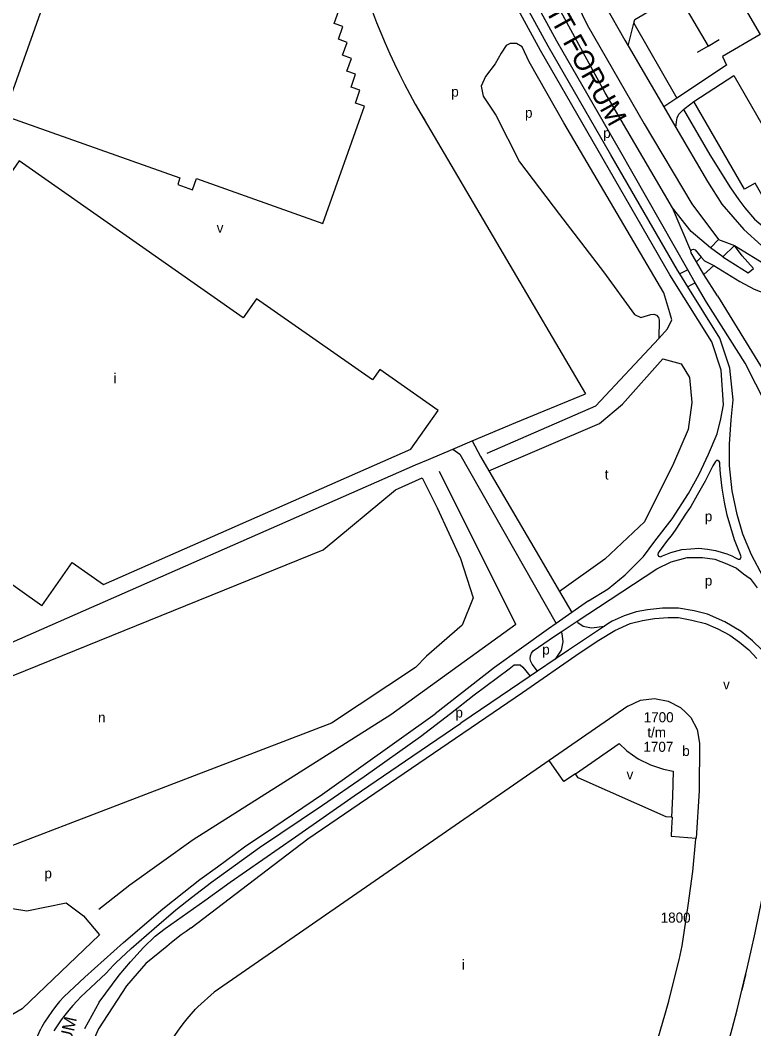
# Model space of a CAD drawing. Extents: x 154765 to 156627, y 383996 to 386132.
# Drawn here: x 155703.2 to 155994.8, y 384500 to 384900.8 of the extents above; entities that cross this region are included whole.
import ezdxf

# ---------------------------------------------------------------- set-up
doc = ezdxf.new("R2010")
doc.units = 0
for name, color, linetype in [('BLT_Basislijn', 7, 'Continuous'), ('BLT_Bebouwing', 7, 'Continuous'), ('BLT_Centroide', 7, 'Continuous'), ('BLT_Huisnummer_reeks', 7, 'Continuous'), ('BLT_Onderverdeling_panden', 7, 'Continuous'), ('BLT_Straatnaam', 7, 'Continuous'), ('BLT_Straatnaam_hoofdweg', 7, 'Continuous'), ('BLT_Vlakafsluiter', 7, 'Continuous')]:
    doc.layers.add(name, color=color, linetype=linetype)

msp = doc.modelspace()

# ---------------------------------------------------------------- linework, layer by layer
at = {"layer": 'BLT_Basislijn'}
for p, q in [((155965.14, 384910.17), (155976.62, 384890.53)), ((155843.24, 384904.14), (155844.83, 384899.94)), ((155844.83, 384899.94), (155846.5, 384895.78)), ((155944.9, 384890.58), (155947.12, 384899.61)), ((155947.12, 384899.61), (155964.19, 384869.82)), ((155846.5, 384895.78), (155848.25, 384891.64)), ((155848.25, 384891.64), (155850.07, 384887.53)), ((155976.62, 384890.53), (155980.95, 384893.19)), ((155850.07, 384887.53), (155851.96, 384883.46)), ((155976.62, 384890.53), (155972.24, 384888.03)), ((155851.96, 384883.46), (155853.92, 384879.42)), ((155853.92, 384879.42), (155855.96, 384875.41)), ((155855.96, 384875.41), (155858.06, 384871.45)), ((155858.06, 384871.45), (155860.24, 384867.52)), ((155964.19, 384869.82), (155959.04, 384866.38)), ((155862.48, 384863.63), (155863.99, 384861.1)), ((155987.12, 384811.23), (156000.44, 384803.04)), ((155968.54, 384801.65), (155965.34, 384800.02)), ((155968.59, 384794.83), (155965.34, 384800.02)), ((155971.5, 384796.52), (155968.54, 384801.65)), ((155957.02, 384774.37), (155960.53, 384778.12)), ((155900.14, 384740.9), (155927.92, 384752.37)), ((155981.67, 384742.4), (155982.74, 384747.99)), ((155985.75, 384741.97), (155986.61, 384749.93)), ((155889.46, 384721.75), (155933.46, 384740.57)), ((155980.16, 384736.38), (155981.67, 384742.4)), ((155985.11, 384732.29), (155985.75, 384741.97)), ((155976.72, 384728.42), (155980.16, 384736.38)), ((155985.11, 384723.68), (155985.11, 384732.29)), ((155973.07, 384720.46), (155976.72, 384728.42)), ((155978.54, 384723.67), (155975.49, 384717.57)), ((155979.55, 384725.5), (155978.54, 384723.67)), ((155979.96, 384725.8), (155979.55, 384725.5)), ((155980.47, 384725.8), (155979.96, 384725.8)), ((155980.97, 384725.5), (155980.47, 384725.8)), ((155981.28, 384724.99), (155980.97, 384725.5)), ((155981.28, 384724.18), (155981.28, 384724.99)), ((155981.48, 384720.52), (155981.28, 384724.18)), ((155986.18, 384713.79), (155985.11, 384723.68)), ((155900.15, 384660.61), (155869.89, 384721.5)), ((155889.46, 384721.75), (155908.25, 384689.69)), ((155968.77, 384712.71), (155973.07, 384720.46)), ((155982.19, 384714.83), (155981.48, 384720.52)), ((155975.49, 384717.57), (155972.24, 384712.09)), ((155983.11, 384709.24), (155982.19, 384714.83)), ((155962.32, 384702.6), (155968.77, 384712.71)), ((155972.24, 384712.09), (155969.7, 384707.62)), ((155988.12, 384704.32), (155986.18, 384713.79)), ((155969.7, 384707.62), (155967.88, 384704.87)), ((155984.22, 384704.16), (155983.11, 384709.24)), ((155967.88, 384704.87), (155965.95, 384701.83)), ((155987.17, 384694.31), (155984.22, 384704.16)), ((155990.48, 384696.58), (155988.12, 384704.32)), ((155955.43, 384693.78), (155962.32, 384702.6)), ((155964.02, 384698.98), (155962.29, 384696.44)), ((155965.95, 384701.83), (155964.02, 384698.98)), ((155962.29, 384696.44), (155960.06, 384693.6)), ((155993.92, 384688.4), (155990.48, 384696.58)), ((155950.92, 384687.76), (155955.43, 384693.78)), ((155960.06, 384693.6), (155957.2, 384689.71)), ((155966.15, 384690.45), (155969.7, 384690.75)), ((155969.7, 384690.75), (155972.95, 384690.96)), ((155972.95, 384690.96), (155976.4, 384690.55)), ((155989.5, 384688.31), (155987.17, 384694.31)), ((155908.25, 384689.69), (155917.54, 384673.85)), ((155943.61, 384680.44), (155950.92, 384687.76)), ((155956.81, 384689.13), (155956.61, 384688.52)), ((155956.61, 384688.52), (155956.91, 384687.86)), ((155957.2, 384689.71), (155956.81, 384689.13)), ((155956.91, 384687.86), (155957.71, 384687.58)), ((155957.71, 384687.58), (155958.53, 384687.91)), ((155958.53, 384687.91), (155961.78, 384689.23)), ((155961.78, 384689.23), (155966.15, 384690.45)), ((155961.89, 384685.61), (155968.34, 384687.33)), ((155968.34, 384687.33), (155974.36, 384687.33)), ((155974.36, 384687.33), (155979.3, 384686.68)), ((155976.4, 384690.55), (155979.55, 384690.04)), ((155979.3, 384686.68), (155984.03, 384684.75)), ((155979.55, 384690.04), (155981.79, 384689.43)), ((155981.79, 384689.43), (155984.02, 384688.72)), ((155984.02, 384688.72), (155986.05, 384687.91)), ((155986.05, 384687.91), (155987.57, 384687.1)), ((155987.57, 384687.1), (155988.59, 384686.59)), ((155989.3, 384686.59), (155989.81, 384687.5)), ((155989.81, 384687.5), (155989.5, 384688.31)), ((155998.44, 384679.58), (155993.92, 384688.4)), ((155933.12, 384667.6), (155956.3, 384682.81)), ((155956.3, 384682.81), (155961.89, 384685.61)), ((155984.03, 384684.75), (155987.9, 384683.03)), ((155987.9, 384683.03), (155990.7, 384680.87)), ((155988.59, 384686.59), (155989.3, 384686.59)), ((155936.94, 384674.85), (155943.61, 384680.44)), ((155990.7, 384680.87), (155993.28, 384678.94)), ((155993.28, 384678.94), (155996.07, 384675.28)), ((155929.13, 384670.04), (155936.94, 384674.85)), ((155917.54, 384673.85), (155922.49, 384665.4)), ((155958.55, 384667.17), (155952.52, 384666.52)), ((155964.8, 384667.17), (155958.55, 384667.17)), ((155971.05, 384666.09), (155964.8, 384667.17)), ((155943.26, 384664.15), (155938.52, 384662)), ((155948, 384665.66), (155943.26, 384664.15)), ((155952.52, 384666.52), (155948, 384665.66)), ((155950.59, 384662.21), (155955.32, 384663.07)), ((155955.32, 384663.07), (155960.71, 384663.5)), ((155960.71, 384663.5), (155964.8, 384663.5)), ((155964.8, 384663.5), (155970.18, 384662.43)), ((155976.43, 384664.8), (155971.05, 384666.09)), ((155983.32, 384661.78), (155976.43, 384664.8)), ((155939.6, 384658.33), (155945.63, 384661.13)), ((155945.63, 384661.13), (155950.59, 384662.21)), ((155970.18, 384662.43), (155975.57, 384661.13)), ((155975.57, 384661.13), (155980.52, 384658.98)), ((155980.52, 384658.98), (155985.26, 384656.39)), ((155989.78, 384657.9), (155983.32, 384661.78)), ((155933.14, 384654.45), (155939.6, 384658.33)), ((155985.26, 384656.39), (155989.14, 384653.59)), ((155994.3, 384654.24), (155989.78, 384657.9)), ((155925.82, 384649.5), (155933.14, 384654.45)), ((155989.14, 384653.59), (155992.8, 384650.58)), ((155992.8, 384650.58), (155996.03, 384647.13)), ((155997.96, 384650.58), (155994.3, 384654.24)), ((155902.9, 384633.69), (155925.82, 384649.5)), ((155905.9, 384647.09), (155905.99, 384648.16)), ((155906.23, 384645.94), (155905.9, 384647.09)), ((155905.99, 384648.16), (155906.41, 384649.26)), ((155906.41, 384649.26), (155907.1, 384650.14)), ((155915.89, 384646.94), (155908.79, 384642.11)), ((155921.12, 384650.51), (155915.89, 384646.94)), ((155891.79, 384643.6), (155868.18, 384625.12)), ((155883.61, 384632.74), (155897.61, 384643.08)), ((155897.61, 384643.08), (155899.55, 384644.59)), ((155899.55, 384644.59), (155901.92, 384644.59)), ((155901.92, 384644.59), (155902.99, 384643.72)), ((155902.99, 384643.72), (155905.9, 384640.14)), ((155906.74, 384644.9), (155906.23, 384645.94)), ((155908.79, 384642.11), (155906.74, 384644.9)), ((155905.9, 384640.14), (155878.3, 384621.52)), ((155908.79, 384642.11), (155905.9, 384640.14)), ((155817.6, 384575.48), (155902.9, 384633.69)), ((155874.18, 384625.29), (155883.61, 384632.74)), ((155823.43, 384593.22), (155868.18, 384625.12)), ((155862.35, 384616.2), (155874.18, 384625.29)), ((155859.27, 384608.48), (155878.3, 384621.52)), ((155839.89, 384600.25), (155862.35, 384616.2)), ((155835.95, 384592.53), (155859.27, 384608.48)), ((155823.43, 384588.93), (155839.89, 384600.25)), ((155804.06, 384580.18), (155823.43, 384593.22)), ((155812.63, 384576.23), (155835.95, 384592.53)), ((155798.4, 384572.11), (155823.43, 384588.93)), ((155792.4, 384572.29), (155804.06, 384580.18)), ((155786.74, 384558.22), (155812.63, 384576.23)), ((155801.44, 384563.18), (155817.6, 384575.48)), ((155779.2, 384558.22), (155798.4, 384572.11)), ((155781.6, 384564.4), (155792.4, 384572.29)), ((155771.22, 384540.07), (155801.44, 384563.18)), ((155774.62, 384559.31), (155781.6, 384564.4)), ((155768.25, 384554.24), (155774.62, 384559.31)), ((155771.36, 384552.12), (155779.2, 384558.22)), ((155776.58, 384550.97), (155786.74, 384558.22)), ((155759.92, 384547.7), (155768.25, 384554.24)), ((155760.9, 384539.85), (155776.58, 384550.97)), ((155765.15, 384547.21), (155771.36, 384552.12)), ((155744.23, 384534.29), (155759.92, 384547.7)), ((155756.49, 384539.85), (155765.15, 384547.21)), ((155747.33, 384531.84), (155756.49, 384539.85)), ((155756.81, 384536.75), (155760.9, 384539.85)), ((155752.24, 384532.33), (155756.81, 384536.75)), ((155728.87, 384520.56), (155744.23, 384534.29)), ((155741.19, 384526.22), (155747.33, 384531.84)), ((155747.01, 384526.61), (155752.24, 384532.33)), ((155720.54, 384512.72), (155728.87, 384520.56)), ((155737.4, 384522.15), (155729.19, 384514.43)), ((155988.13, 384507.59), (155991.54, 384521.43)), ((155991.54, 384521.43), (155990.07, 384515.31)), ((155986.14, 384500), (155988.13, 384507.59)), ((155982.27, 384486.09), (155986.13, 384499.98)), ((155986.13, 384499.98), (155986.14, 384500))]:
    msp.add_line(p, q, dxfattribs=at)
for points in [[(155962.52, 384826.27), (155935.77, 384871.91), (155901.3, 384935.31), (155901.3, 384935.31), (155894.58, 384950.8), (155887.34, 384971.47), (155883.48, 384986.96), (155879.92, 385009.42), (155878.55, 385052.4), (155881.91, 385077.92)], [(155881.91, 385077.92), (155881.11, 385062.39), (155881.31, 385049.86), (155882.44, 385026.52), (155885.1, 385009.65), (155885.1, 385009.65), (155888.56, 384996.23), (155896.24, 384972.11), (155908.62, 384940.24), (155908.62, 384940.24), (155928.62, 384898.94), (155951.25, 384859.63), (155970.21, 384827.91), (155980.73, 384813.62), (155980.73, 384813.62)], [(155982.74, 384747.99), (155981.79, 384761.81), (155978.09, 384773), (155961.45, 384799.64), (155934.97, 384845.54), (155909.95, 384888.82), (155891.81, 384922.17), (155885.25, 384935.64), (155874.71, 384962.88), (155867.9, 384989.38), (155864.81, 385012.56), (155863.83, 385032.74), (155864.43, 385050.58)], [(155965.34, 384800.02), (155964.45, 384801.44), (155938, 384847.29), (155913, 384890.54), (155894.92, 384923.78), (155888.46, 384937.04), (155878.05, 384963.95), (155871.35, 384990.05), (155868.3, 385012.88), (155867.33, 385032.77), (155867.93, 385050.46)], [(155968.54, 384801.65), (155941.46, 384849.29), (155916.49, 384892.49), (155898.47, 384925.61), (155892.13, 384938.64), (155881.86, 384965.17), (155875.28, 384990.81), (155872.29, 385013.24), (155871.33, 385032.8), (155871.93, 385050.32)], [(155947.12, 384899.61), (155947.5, 384901.16), (155977.2, 384918.58), (155983.01, 384919.78), (155997.35, 384895.09), (155982.3, 384886.45), (155983.87, 384882.97), (155964.19, 384869.82)], [(155933.89, 384910.23), (155935.71, 384906.61), (155943.51, 384892.95), (155944.9, 384890.58)], [(155902.76, 384890.22), (155900.53, 384891.63), (155897.89, 384891.58), (155896.4, 384890.8), (155894.39, 384887.76), (155892.02, 384883.48), (155888.13, 384878.41), (155886.47, 384874.68), (155887.26, 384870.67), (155892.24, 384863.08), (155901.69, 384844.53), (155917.59, 384823.58), (155935.09, 384800.78), (155947.43, 384783.89), (155949.84, 384782.68), (155953.85, 384783.87), (155955, 384783.98), (155956.07, 384783.57), (155956.84, 384782.71), (155957.14, 384781.59), (155957.02, 384774.37)], [(155960.53, 384778.12), (155962.18, 384781.7), (155961.37, 384784.57), (155958.96, 384792.48), (155919.25, 384859.98), (155905.53, 384884.34), (155902.76, 384890.22)], [(155944.9, 384890.58), (155959.04, 384866.38)], [(155970.97, 384868.46), (155986.8, 384878.86), (156002.87, 384850.99), (156023.43, 384862.57)], [(155860.24, 384867.52), (155862.48, 384863.63), (155927.92, 384752.37)], [(155966.85, 384865.29), (155967.54, 384865.9), (155970.97, 384868.46)], [(156023.43, 384862.57), (156027.07, 384856.44), (156031.38, 384858.87), (156045.39, 384835.44), (156041.27, 384832.4), (156048.9, 384819.1), (156046.53, 384817.73), (156046.55, 384814.94), (156039.42, 384813.54), (156033.28, 384812.76), (156025.61, 384812.76), (156017.41, 384814.12), (156009.98, 384816.64), (156006.07, 384819.03), (156003.77, 384821.25), (155995.3, 384836.12), (155991.05, 384833.74), (155970.97, 384868.46)], [(155959.04, 384866.38), (155963.85, 384858.14)], [(155963.85, 384858.14), (155964.06, 384860.39), (155964.35, 384861.98), (155964.99, 384863.47), (155965.73, 384864.32), (155966.85, 384865.29)], [(155966.85, 384865.29), (155977.34, 384847.26), (155985.46, 384834.23), (155988.81, 384829.4), (155991.2, 384826.31), (155995.09, 384821.78), (156001.03, 384816.78), (156007.69, 384812.8), (156014.81, 384809.96), (156022.3, 384808.27), (156030.91, 384807.9), (156039.49, 384808.74), (156053.51, 384811.77)], [(155963.85, 384858.14), (155976.36, 384836.75), (155982.06, 384827.68), (155990.84, 384817.59), (155997.87, 384811.31), (156000, 384809.93), (156006.15, 384806.79), (156012.47, 384804.16), (156019.06, 384802.43), (156024.57, 384801.78), (156031.1, 384801.56), (156038.42, 384802.32), (156044.23, 384803.38), (156049.74, 384804.57), (156053.13, 384805.44)], [(155977.59, 384810.4), (155969.83, 384816.91), (155962.52, 384826.27)], [(155977.57, 384810.42), (155980.73, 384813.62)], [(155980.73, 384813.62), (155987.12, 384811.23), (155987.12, 384811.23)], [(155987.12, 384811.23), (155982.5, 384806.83)], [(155994.61, 384802.19), (155990.13, 384807.18), (155987.12, 384811.23)], [(155969.8, 384809.14), (155970.23, 384809.67), (155970.87, 384809.79), (155971.52, 384809.51), (155973.85, 384806.68), (155973.85, 384806.68)], [(155971.99, 384804.85), (155969.86, 384808.37), (155969.8, 384809.14)], [(155977.59, 384810.4), (155977.57, 384810.42)], [(155982.5, 384806.83), (155977.59, 384810.4)], [(155971.99, 384804.85), (155973.85, 384806.68)], [(155974.95, 384799.82), (155971.99, 384804.85)], [(155973.85, 384806.68), (155975.21, 384805.26), (155978.85, 384803.32)], [(155974.95, 384799.82), (155978.85, 384803.32)], [(155978.85, 384803.32), (155989.28, 384796.96), (155994.94, 384794), (156001.39, 384791.48), (156009.15, 384789.21), (156009.15, 384789.21), (156017.42, 384787.74)], [(155982.5, 384806.83), (155992.5, 384800.45), (155994.61, 384802.19)], [(155980.29, 384791.35), (155974.95, 384799.82)], [(155971.5, 384796.52), (155968.59, 384794.83)], [(156008.49, 384728.25), (156003.96, 384739.77), (155991.3, 384764.52), (155976.03, 384788.73), (155971.5, 384796.52)], [(155986.61, 384749.93), (155985.25, 384762.49), (155981.28, 384774.5), (155968.59, 384794.83)], [(155980.29, 384791.35), (155998.48, 384761.75), (155998.51, 384761.7)], [(155888.77, 384728.75), (155931.95, 384747.58), (155957.02, 384774.37)], [(155965.89, 384764.23), (155969.2, 384758.84), (155970.15, 384748.88), (155968.68, 384738.18), (155962.89, 384724.63), (155951.38, 384701.5), (155935.56, 384686.69), (155917.54, 384673.85)], [(155933.46, 384740.57), (155942.6, 384748.23), (155958.64, 384766.23), (155965.89, 384764.23)], [(155882.82, 384733.61), (155900.14, 384740.9)], [(155875.21, 384730.41), (155882.82, 384733.61)], [(155882.82, 384733.61), (155886.11, 384727.47), (155889.46, 384721.75)], [(155865.44, 384726.3), (155875.21, 384730.41)], [(155875.21, 384730.41), (155877.9, 384728.42), (155916.28, 384661.05)], [(155696.4, 384652.06), (155860.39, 384724.09)], [(155860.39, 384724.09), (155865.44, 384726.3)], [(155578.26, 384560.55), (155625.71, 384609.45), (155630.96, 384612.32), (155823.58, 384690.32), (155852.37, 384714.19), (155862.96, 384718.92)], [(155862.96, 384718.92), (155868.89, 384707.02), (155878.23, 384686.96), (155883.19, 384671.24), (155878.85, 384660.35), (155864.72, 384648.14), (155860.33, 384643.55), (155826.95, 384621.49), (155611.26, 384538.75), (155578.26, 384560.55)], [(155929.13, 384670.04), (155922.49, 384665.4)], [(155924.52, 384661.93), (155933.12, 384667.6)], [(155922.49, 384665.4), (155916.28, 384661.05)], [(155900.15, 384660.61), (155850.49, 384624.75), (155771.92, 384575.05), (155746.84, 384557.03), (155734.42, 384547.42)], [(155916.28, 384661.05), (155913.22, 384658.91), (155891.79, 384643.6)], [(155918.16, 384657.74), (155924.52, 384661.93)], [(155935.41, 384660.01), (155921.12, 384650.51)], [(155924.52, 384661.93), (155924.79, 384661.47), (155927.01, 384659.98), (155930.23, 384659.41), (155935.41, 384660.01)], [(155938.52, 384662), (155937.23, 384661.22), (155935.41, 384660.01)], [(155907.1, 384650.14), (155915.59, 384656.04), (155918.16, 384657.74)], [(155918.16, 384657.74), (155918.51, 384657.12), (155918.93, 384653.75), (155918.18, 384650.44), (155915.89, 384646.94)], [(155991.54, 384521.43), (155991.88, 384522.85), (155993.64, 384530.51), (155995.32, 384538.19), (155996.93, 384545.89), (155998.45, 384553.6), (155999.9, 384561.32), (156000.6, 384565.31)], [(155628.26, 384531.13), (155644.65, 384541.35), (155665.3, 384548.05), (155687.79, 384549.74), (155705.92, 384546.85), (155721.5, 384550.01), (155728.41, 384544.89), (155734.71, 384537.35)], [(155771.22, 384540.07), (155769.19, 384538.72), (155767.2, 384537.31), (155763.37, 384534.29), (155761.53, 384532.69), (155753.18, 384525.93), (155749.68, 384521.98), (155745.5, 384517.01), (155734.37, 384500)], [(155734.71, 384537.35), (155704.01, 384507.98), (155693.62, 384502.02), (155686.13, 384498.37), (155680.99, 384496.61), (155675.34, 384495.78), (155669.38, 384495.69), (155664.51, 384496.83), (155655.33, 384500.35)], [(155734.65, 384510.61), (155742.58, 384521.33), (155747.01, 384526.61)], [(155737.4, 384522.15), (155740.35, 384525.34), (155741.19, 384526.22)], [(155729.19, 384514.43), (155727.47, 384512.78), (155725.77, 384511.03), (155724.12, 384509.23), (155722.54, 384507.37), (155721.01, 384505.46), (155719.55, 384503.51), (155718.15, 384501.51), (155717.16, 384500)], [(155720.54, 384512.72), (155718.9, 384510.81), (155717.31, 384508.85), (155715.79, 384506.84), (155714.33, 384504.78), (155712.94, 384502.68), (155711.79, 384500.82), (155711.41, 384500)], [(155734.65, 384510.61), (155728.75, 384500)], [(155707.25, 384490.59), (155711.4, 384499.98)], [(155711.41, 384500), (155711.4, 384499.98)], [(155717.15, 384499.98), (155716.64, 384499.15)], [(155717.16, 384500), (155717.15, 384499.98)], [(155734.36, 384499.98), (155729.52, 384489.29), (155727.39, 384483.04), (155726.56, 384479.17), (155725.82, 384475.28), (155725.15, 384471.38), (155724.56, 384467.46), (155724.06, 384463.54), (155723.63, 384459.6), (155723.28, 384455.66), (155723.01, 384451.71), (155722.82, 384447.75), (155722.71, 384443.8), (155722.68, 384439.84), (155722.73, 384435.88), (155722.86, 384431.93), (155723.07, 384427.97), (155723.37, 384424.03), (155723.74, 384420.08), (155724.18, 384416.15), (155724.71, 384412.23), (155725.32, 384408.32), (155726.01, 384404.42), (155726.76, 384400.6)], [(155728.75, 384500), (155728.74, 384499.98)], [(155734.37, 384500), (155734.36, 384499.98)]]:
    msp.add_lwpolyline(points, dxfattribs=at)
at = {"layer": 'BLT_Bebouwing'}
for p, q in [((155711.84, 384668.11), (155686.21, 384686.06)), ((155944.73, 384628.25), (155913.51, 384606.65)), ((155913.51, 384606.65), (155780.36, 384514.56)), ((155780.36, 384514.56), (155773.8, 384508.66))]:
    msp.add_line(p, q, dxfattribs=at)
for points in [[(155738.59, 384980.96), (155696.77, 384862.93), (155766.72, 384838.14), (155765.85, 384835.53), (155771.73, 384833.45), (155773.3, 384837.89), (155823.53, 384820.05), (155840.07, 384866.64), (155836.44, 384867.91), (155838.22, 384873.01), (155834.75, 384874.24), (155836.54, 384879.34), (155833.04, 384880.57), (155834.86, 384885.65), (155831.37, 384886.9), (155833.18, 384891.99), (155829.68, 384893.23), (155831.49, 384898.33), (155827.99, 384899.57), (155829.8, 384904.65)], [(155858.53, 384730.34), (155869.31, 384745.72), (155846.14, 384761.95), (155843.27, 384757.84), (155797.17, 384790.14), (155791.89, 384782.58), (155702.83, 384844.99), (155690.4, 384827.18), (155680.89, 384833.83), (155661.81, 384804.02), (155670.12, 384798.2), (155655.45, 384777.25), (155647.14, 384783.07), (155625.66, 384754.98), (155635.16, 384748.3)], [(155711.84, 384668.11), (155723.82, 384685.29), (155736.34, 384676.51), (155858.53, 384730.34)], [(155944.73, 384628.25), (155949.7, 384630.57), (155955.29, 384631.29), (155960.7, 384630.24), (155965.64, 384627.69), (155967.72, 384625.67), (155969.74, 384623.74), (155972.22, 384618.99), (155973.21, 384613.51)], [(155923.88, 384601.32), (155941.26, 384613.33), (155944.33, 384610.48), (155948.78, 384607.3), (155953.67, 384604.84), (155958.87, 384603.13), (155962.72, 384602.4), (155962.44, 384592.43), (155962.02, 384584.12)], [(155973.21, 384613.51), (155973.01, 384594.51), (155971.82, 384575.76)], [(155962.02, 384584.12), (155960.01, 384584.22), (155925.02, 384599.67), (155923.88, 384601.32)], [(155964.09, 384523.28), (155965.06, 384527.45), (155966.28, 384533), (155968.68, 384548.99), (155970.52, 384562.49), (155971.8, 384575.55), (155971.82, 384575.76)], [(155957.83, 384500), (155959.42, 384505.43), (155960.95, 384510.91), (155964.09, 384523.28)], [(155766.49, 384500), (155767.99, 384501.99), (155769.57, 384503.96), (155771.2, 384505.87), (155772.9, 384507.73), (155773.8, 384508.66)], [(155759.36, 384489.73), (155766.48, 384499.98)], [(155766.48, 384499.98), (155766.49, 384500)], [(155943.75, 384460.77), (155945.9, 384466.03), (155947.99, 384471.31), (155949.99, 384476.63), (155951.93, 384481.98), (155953.78, 384487.35), (155955.56, 384492.74), (155957.27, 384498.16), (155957.82, 384499.98)], [(155957.82, 384499.98), (155957.83, 384500)]]:
    msp.add_lwpolyline(points, dxfattribs=at)
at = {"layer": 'BLT_Onderverdeling_panden'}
for points in [[(155923.88, 384601.32), (155919.25, 384598.25), (155913.51, 384606.65)], [(155962.02, 384584.12), (155962.32, 384584.11), (155962.1, 384579.88), (155961.91, 384576.56), (155971.82, 384575.76)]]:
    msp.add_lwpolyline(points, dxfattribs=at)
at = {"layer": 'BLT_Vlakafsluiter'}
msp.add_line((155969.8, 384809.14), (155962.52, 384826.27), dxfattribs=at)

# ---------------------------------------------------------------- texts
at = {"layer": 'BLT_Centroide'}
for s, p in [('p', (155874.54, 384870.43)), ('p', (155903.86, 384862.06)), ('p', (155934.93, 384854.02)), ('v', (155781.31, 384816.33)), ('i', (155740.35, 384756.56)), ('t', (155935.56, 384718.29)), ('p', (155975.31, 384701.69)), ('p', (155975.31, 384676.12)), ('p', (155910.7, 384648.73)), ('v', (155982.56, 384634.9)), ('p', (155876.2, 384623.69)), ('n', (155734.17, 384621.75)), ('b', (155966.34, 384608.44)), ('v', (155944.22, 384599.11)), ('p', (155712.87, 384559.79)), ('i', (155878.72, 384523.5))]:
    msp.add_text(s, height=4, dxfattribs=at).set_placement(p)
at = {"layer": 'BLT_Huisnummer_reeks'}
for s, p in [('1700', (155951.02, 384621.81)), ('t/m', (155952.46, 384615.81)), ('1707', (155950.9, 384610.07)), ('1800', (155957.77, 384542.18))]:
    msp.add_text(s, height=4, dxfattribs=at).set_placement(p)
at = {"layer": 'BLT_Straatnaam'}
msp.add_text('FLIGHT FORUM', height=5, rotation=77.3725, dxfattribs=at).set_placement((155714.85, 384455.22))
at = {"layer": 'BLT_Straatnaam_hoofdweg'}
msp.add_text('FLIGHT FORUM', height=8, rotation=299, dxfattribs=at).set_placement((155898.78, 384928.19))

doc.saveas('drawing.dxf')
